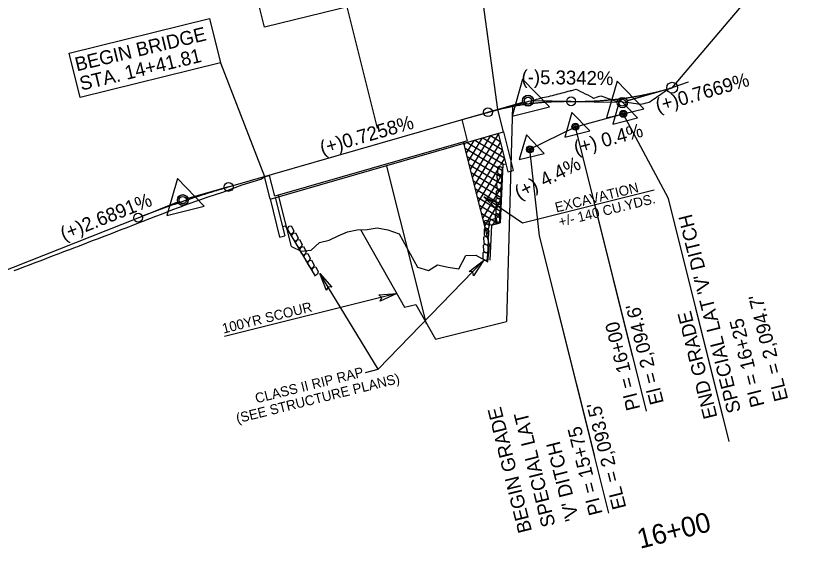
# Model space of a CAD drawing. Extents: x 1030663 to 1033857, y 654635 to 657099.
# Drawn here: x 1031298.2 to 1031692.3, y 655961.2 to 656230.1 of the extents above; entities that cross this region are included whole.
import ezdxf

# ---------------------------------------------------------------- set-up
doc = ezdxf.new("R2010")
doc.units = 0
for name, color, linetype in [('Default', 7, 'Continuous'), ('Exist Vertical Profile Ground Line', 7, 'Continuous'), ('Exist Vertical Profile Horizontal Axis Label Major', 7, 'Continuous'), ('Prop CMT PFL Bottom Envelope', 7, 'Continuous'), ('Prop Grid Mask', 7, 'Continuous'), ('Prop PFL Text', 7, 'Continuous'), ('Prop PFL VPI Symbol CELL', 7, 'Continuous'), ('Prop Terminator CELL', 7, 'Continuous'), ('Prop Vertical Profile Curve Label', 7, 'Continuous'), ('Prop Vertical Profile Ditch Grade Right', 7, 'Continuous'), ('Prop Vertical Profile Ditch Grade Right Label', 7, 'Continuous'), ('Prop Vertical Profile Grade', 7, 'Continuous'), ('Prop Vertical Profile Grade Label', 7, 'Continuous'), ('Prop VPI Ditch Grade Right Label', 7, 'Continuous'), ('Prop VPI Label', 7, 'Continuous')]:
    doc.layers.add(name, color=color, linetype=linetype)

msp = doc.modelspace()

# ---------------------------------------------------------------- linework, layer by layer
at = {"layer": 'Default'}
for p, q in [((1031480.61, 656173.24), (1031465.38, 656234.47)), ((1031548.7, 656184.39), (1031545.65, 656075.66)), ((1031543.8, 656154.93), (1031545.3, 656155.31)), ((1031505.23, 656074.48), (1031485.37, 656154.12)), ((1031543.8, 656154.93), (1031542.41, 656125.45)), ((1031430.65, 656138.54), (1031431.11, 656138.26)), ((1031434.22, 656123.85), (1031432.78, 656123.49)), ((1031433.94, 656123.78), (1031432.78, 656123.49)), ((1031434.22, 656123.85), (1031449.22, 656098.58)), ((1031538.14, 656124.38), (1031537.3, 656106.59)), ((1031538.14, 656124.38), (1031542.41, 656125.45)), ((1031472.03, 656122.07), (1031494.29, 656082.9)), ((1031494.29, 656082.9), (1031499.91, 656084.3)), ((1031499.91, 656084.3), (1031509.89, 656066.74)), ((1031509.89, 656066.74), (1031545.65, 656075.66))]:
    msp.add_line(p, q, dxfattribs=at)
for points in [[(1031543.29, 656149.86), (1031543.49, 656151.03), (1031543.56, 656153.2), (1031542.08, 656153.93), (1031541.07, 656153.62), (1031541.13, 656150.77), (1031542.11, 656149.9), (1031543.29, 656149.86)], [(1031543.07, 656145.78), (1031543.27, 656146.95), (1031543.35, 656149.12), (1031541.86, 656149.85), (1031540.85, 656149.54), (1031540.91, 656146.69), (1031541.9, 656145.82), (1031543.07, 656145.78)], [(1031542.87, 656141.87), (1031543.07, 656143.03), (1031543.14, 656145.21), (1031541.65, 656145.93), (1031540.64, 656145.63), (1031540.71, 656142.78), (1031541.69, 656141.91), (1031542.87, 656141.87)], [(1031620.06, 656141.89), (1031553.7, 656125.34), (1031534.29, 656138.61)], [(1031542.73, 656137.7), (1031542.93, 656138.87), (1031543, 656141.04), (1031541.51, 656141.77), (1031540.5, 656141.46), (1031540.57, 656138.61), (1031541.55, 656137.74), (1031542.73, 656137.7)], [(1031542.55, 656133.68), (1031542.75, 656134.85), (1031542.82, 656137.03), (1031541.33, 656137.75), (1031540.32, 656137.45), (1031540.39, 656134.6), (1031541.37, 656133.72), (1031542.55, 656133.68)], [(1031542.38, 656129.76), (1031542.58, 656130.93), (1031542.66, 656133.1), (1031541.17, 656133.83), (1031540.16, 656133.52), (1031540.22, 656130.67), (1031541.21, 656129.8), (1031542.38, 656129.76)], [(1031537.19, 656124.49), (1031538.37, 656124.61), (1031540.48, 656125.13), (1031540.78, 656126.76), (1031540.21, 656127.65), (1031537.48, 656126.82), (1031536.91, 656125.63), (1031537.19, 656124.49)], [(1031542.08, 656125.87), (1031542.28, 656127.04), (1031542.36, 656129.21), (1031540.87, 656129.94), (1031539.86, 656129.63), (1031539.92, 656126.78), (1031540.9, 656125.91), (1031542.08, 656125.87)], [(1031436.97, 656119.6), (1031436.24, 656120.54), (1031435.16, 656122.42), (1031436.13, 656123.76), (1031437.16, 656123.97), (1031438.45, 656121.42), (1031437.99, 656120.19), (1031436.97, 656119.6)], [(1031536.67, 656122.62), (1031536.87, 656123.79), (1031536.94, 656125.97), (1031535.46, 656126.69), (1031534.45, 656126.39), (1031534.51, 656123.53), (1031535.49, 656122.66), (1031536.67, 656122.62)], [(1031439.08, 656116.1), (1031438.35, 656117.04), (1031437.26, 656118.93), (1031438.24, 656120.27), (1031439.27, 656120.47), (1031440.55, 656117.92), (1031440.09, 656116.69), (1031439.08, 656116.1)], [(1031536.53, 656118.46), (1031536.73, 656119.63), (1031536.8, 656121.8), (1031535.31, 656122.53), (1031534.3, 656122.22), (1031534.37, 656119.37), (1031535.35, 656118.5), (1031536.53, 656118.46)], [(1031441.09, 656112.74), (1031440.37, 656113.68), (1031439.28, 656115.57), (1031440.25, 656116.91), (1031441.29, 656117.11), (1031442.57, 656114.56), (1031442.11, 656113.33), (1031441.09, 656112.74)], [(1031536.35, 656114.44), (1031536.55, 656115.61), (1031536.62, 656117.78), (1031535.14, 656118.51), (1031534.12, 656118.21), (1031534.19, 656115.35), (1031535.17, 656114.48), (1031536.35, 656114.44)], [(1031443.17, 656109.13), (1031442.45, 656110.07), (1031441.36, 656111.95), (1031442.33, 656113.29), (1031443.37, 656113.5), (1031444.65, 656110.95), (1031444.19, 656109.72), (1031443.17, 656109.13)], [(1031536.18, 656110.52), (1031536.38, 656111.69), (1031536.46, 656113.86), (1031534.97, 656114.59), (1031533.96, 656114.28), (1031534.02, 656111.43), (1031535.01, 656110.56), (1031536.18, 656110.52)], [(1031445.22, 656105.67), (1031444.49, 656106.61), (1031443.4, 656108.49), (1031444.38, 656109.83), (1031445.41, 656110.04), (1031446.69, 656107.49), (1031446.23, 656106.26), (1031445.22, 656105.67)], [(1031535.88, 656106.63), (1031536.08, 656107.79), (1031536.16, 656109.97), (1031534.67, 656110.69), (1031533.66, 656110.39), (1031533.72, 656107.54), (1031534.71, 656106.67), (1031535.88, 656106.63)], [(1031447.21, 656102.28), (1031446.48, 656103.22), (1031445.39, 656105.1), (1031446.37, 656106.44), (1031447.4, 656106.65), (1031448.68, 656104.1), (1031448.22, 656102.87), (1031447.21, 656102.28)], [(1031474.6, 656050.03), (1031481.01, 656051.62), (1031534.12, 656106.4)], [(1031449.3, 656098.99), (1031448.57, 656099.92), (1031447.49, 656101.81), (1031448.46, 656103.15), (1031449.49, 656103.36), (1031450.78, 656100.81), (1031450.32, 656099.57), (1031449.3, 656098.99)], [(1031481.01, 656051.62), (1031451.48, 656099.86)], [(1031490.39, 656089.75), (1031403.4, 656068.06)]]:
    msp.add_lwpolyline(points, dxfattribs=at)
at = {"layer": 'Exist Vertical Profile Ground Line'}
for p, q in [((1031525.96, 656166.87), (1031523.27, 656177.63)), ((1031525.96, 656166.87), (1031428.85, 656138.86)), ((1031537, 656114.32), (1031524.03, 656166.31)), ((1031423.97, 656148.84), (1031426.22, 656149.4)), ((1031428.85, 656138.86), (1031426.22, 656149.4)), ((1031437.24, 656113.49), (1031430.77, 656139.41))]:
    msp.add_line(p, q, dxfattribs=at)
for points in [[(1031523.27, 656177.63), (1031546, 656183.78), (1031552.12, 656185.56), (1031555.91, 656186.58), (1031556.9, 656186.84), (1031557.88, 656187.1), (1031558.87, 656187.36), (1031559.86, 656187.62), (1031560.84, 656187.88), (1031561.83, 656188.13), (1031562.82, 656188.39), (1031563.8, 656188.66), (1031564.79, 656188.91), (1031565.79, 656189.09), (1031566.89, 656189.29), (1031567.79, 656189.52), (1031568.78, 656189.78), (1031569.76, 656190.04), (1031570.75, 656190.3), (1031571.74, 656190.55), (1031572.72, 656190.81), (1031573.71, 656191.07), (1031574.7, 656191.33), (1031575.68, 656191.59), (1031576.67, 656191.85), (1031577.66, 656192.1), (1031577.97, 656192.19), (1031578.64, 656192.35), (1031579.63, 656192.6), (1031580.71, 656192.87), (1031581.79, 656192.37), (1031582.98, 656191.81), (1031584.18, 656191.23), (1031585.38, 656190.63), (1031586.58, 656190.02), (1031587.79, 656189.38), (1031589.01, 656188.73), (1031589.57, 656188.42), (1031590.09, 656188.59), (1031591.07, 656188.9), (1031592.05, 656189.19), (1031593.26, 656189.53), (1031594.13, 656189.25), (1031595.28, 656188.87), (1031596.43, 656188.48), (1031597.58, 656188.08), (1031598.73, 656187.67), (1031599.89, 656187.24), (1031601.04, 656186.82), (1031602.12, 656186.74), (1031603.19, 656186.65), (1031604.27, 656186.54), (1031605.35, 656186.43), (1031606.43, 656186.31), (1031607.51, 656186.17), (1031608.6, 656186.03), (1031609.69, 656185.88), (1031611.04, 656185.67), (1031611.87, 656185.55), (1031613.06, 656185.36), (1031613.97, 656185.55), (1031614.97, 656185.76), (1031615.97, 656185.98), (1031616.97, 656186.19), (1031617.57, 656186.31), (1031617.92, 656186.57), (1031618.81, 656187.21), (1031619.71, 656187.84), (1031620.6, 656188.47), (1031621.5, 656189.1), (1031622.39, 656189.72), (1031623.29, 656190.33), (1031624.19, 656190.94), (1031625.09, 656191.54), (1031626.36, 656192.39), (1031627.42, 656193.05), (1031627.86, 656193.44), (1031629.13, 656193.75), (1031637.36, 656196.59), (1031637.36, 656196.59)], [(1031297.49, 656101.37), (1031299.41, 656102.11), (1031302.3, 656103.22), (1031305.2, 656104.32), (1031308.09, 656105.43), (1031310.98, 656106.54), (1031313.87, 656107.65), (1031316.76, 656108.76), (1031319.65, 656109.87), (1031321.39, 656110.54), (1031322.55, 656110.98), (1031323.5, 656111.34), (1031323.82, 656111.45), (1031325.45, 656112.06), (1031328.34, 656113.14), (1031329.49, 656113.57), (1031330.74, 656114.06), (1031331.23, 656114.25), (1031334.12, 656115.37), (1031337.01, 656116.49), (1031339.9, 656117.61), (1031342.79, 656118.73), (1031345.68, 656119.85), (1031348.57, 656120.97), (1031351.46, 656122.08), (1031354.35, 656123.2), (1031355.64, 656123.7), (1031357.24, 656124.32), (1031360.13, 656125.45), (1031363.01, 656126.58), (1031363.62, 656126.81), (1031365.9, 656127.69), (1031368.79, 656128.81), (1031371.68, 656129.92), (1031374.57, 656131.03), (1031377.47, 656132.15), (1031380.36, 656133.26), (1031381.79, 656133.81), (1031383.26, 656134.33), (1031386.17, 656135.36), (1031389.08, 656136.39), (1031391.99, 656137.41), (1031392.45, 656137.58), (1031395.33, 656138.66), (1031402.61, 656140.95), (1031412.43, 656144.62), (1031421.86, 656147.54), (1031423.97, 656148.84)], [(1031437.24, 656113.49), (1031442.14, 656111.13), (1031447.16, 656111.66), (1031451.35, 656115.5), (1031456.21, 656116.71), (1031460.8, 656118.94), (1031465.46, 656120.91), (1031470.34, 656122.03), (1031475.46, 656122.14), (1031480.4, 656123.01), (1031485.82, 656121.93), (1031491.45, 656120), (1031500.81, 656103.13), (1031506.38, 656101.45), (1031510.81, 656104.36), (1031516.25, 656103.19), (1031521.63, 656102.28), (1031525.13, 656108.92), (1031530.22, 656109.2), (1031536.23, 656105.74), (1031537, 656114.32)]]:
    msp.add_lwpolyline(points, dxfattribs=at)
at = {"layer": 'Prop CMT PFL Bottom Envelope'}
for p, q in [((1031544.13, 656171.38), (1031541.32, 656182.67)), ((1031426.46, 656137.46), (1031544.13, 656171.38)), ((1031544.13, 656171.38), (1031548.97, 656151.97)), ((1031525.43, 656160.72), (1031529.26, 656167.09)), ((1031526.46, 656156.6), (1031533.49, 656168.31)), ((1031527.48, 656152.48), (1031537.72, 656169.53)), ((1031528.51, 656148.37), (1031541.6, 656170.16)), ((1031529.71, 656167.22), (1031544.56, 656158.3)), ((1031533.65, 656168.35), (1031543.53, 656162.42)), ((1031537.59, 656169.49), (1031542.51, 656166.53)), ((1031541.46, 656170.71), (1031546.3, 656151.3)), ((1031524.4, 656164.83), (1031525.03, 656165.87)), ((1031524.82, 656163.16), (1031543.66, 656151.84)), ((1031525.78, 656166.09), (1031544.14, 656155.05)), ((1031529.54, 656144.25), (1031542.63, 656166.04)), ((1031530.56, 656140.13), (1031543.65, 656161.92)), ((1031525.85, 656159.04), (1031543.49, 656148.44)), ((1031542.8, 656154.68), (1031544.68, 656157.81)), ((1031526.87, 656154.93), (1031543.33, 656145.04)), ((1031531.59, 656136.02), (1031542.64, 656154.4)), ((1031546.3, 656151.3), (1031548.97, 656151.97)), ((1031426.42, 656137.64), (1031423.62, 656148.84)), ((1031527.9, 656150.81), (1031543.17, 656141.63)), ((1031532.61, 656131.9), (1031543.58, 656150.14)), ((1031528.93, 656146.69), (1031543.01, 656138.23)), ((1031533.64, 656127.78), (1031543.28, 656143.82)), ((1031529.95, 656142.58), (1031541.74, 656135.49)), ((1031426.42, 656137.64), (1031431.26, 656118.23)), ((1031429.09, 656138.3), (1031433.92, 656118.9)), ((1031530.98, 656138.46), (1031542.69, 656131.42)), ((1031534.72, 656123.76), (1031542.98, 656137.5)), ((1031532.01, 656134.34), (1031542.53, 656128.02)), ((1031533.13, 656130.17), (1031541.42, 656125.19)), ((1031538.67, 656124.5), (1031542.68, 656131.18)), ((1031534.06, 656126.11), (1031537.28, 656124.17)), ((1031535.08, 656121.99), (1031536.83, 656120.94)), ((1031535.69, 656119.55), (1031536.86, 656121.49)), ((1031431.26, 656118.23), (1031433.92, 656118.9))]:
    msp.add_line(p, q, dxfattribs=at)
at = {"layer": 'Prop Grid Mask'}
for points in [[(1031413.95, 656263.49), (1031510.89, 656287.51), (1031520.64, 656248.16), (1031423.7, 656224.15)], [(1031325.16, 656211.18), (1031395.98, 656228.62), (1031401.5, 656206.18), (1031330.68, 656188.74)]]:
    msp.add_lwpolyline(points, close=True, dxfattribs=at)
at = {"layer": 'Prop PFL VPI Symbol CELL'}
for p, q in [((1031553.77, 656198.03), (1031548.45, 656179.39)), ((1031553.77, 656198.03), (1031567.29, 656184.09)), ((1031601.36, 656197.04), (1031596.04, 656178.4)), ((1031601.36, 656197.04), (1031614.88, 656183.1)), ((1031548.45, 656179.39), (1031567.29, 656184.09)), ((1031596.04, 656178.4), (1031614.88, 656183.1)), ((1031379.73, 656147.87), (1031374.41, 656129.23)), ((1031379.73, 656147.87), (1031393.26, 656133.93)), ((1031374.41, 656129.23), (1031393.26, 656133.93))]:
    msp.add_line(p, q, dxfattribs=at)
for centre, radius in [((1031556.49, 656187.14), 2.62), ((1031556.49, 656187.14), 1.8), ((1031604.08, 656186.15), 2.62), ((1031604.08, 656186.15), 1.8), ((1031382.46, 656136.98), 2.62), ((1031382.46, 656136.98), 1.8)]:
    msp.add_circle(centre, radius, dxfattribs=at)
at = {"layer": 'Prop Terminator CELL'}
for points in [[(1031540.85, 656132.25), (1031534.29, 656138.61), (1031542.67, 656134.83), (1031540.81, 656134.15)], [(1031526.75, 656101.01), (1031534.12, 656106.4), (1031528.97, 656098.79), (1031528.63, 656100.73)], [(1031454.86, 656091.38), (1031451.48, 656099.86), (1031457.57, 656092.98), (1031455.61, 656093.13)], [(1031481.28, 656089.08), (1031490.39, 656089.75), (1031482, 656086.01), (1031482.73, 656087.84)]]:
    msp.add_lwpolyline(points, close=True, dxfattribs=at)
at = {"layer": 'Prop Vertical Profile Curve Label'}
for centre in [(1031578.23, 656186.79), (1031536.3, 656181.32), (1031405.54, 656143.63), (1031359.95, 656128.05)]:
    msp.add_circle(centre, 2.25, dxfattribs=at)
at = {"layer": 'Prop Vertical Profile Ditch Grade Right'}
msp.add_lwpolyline([(1031557.47, 656162.58), (1031580.39, 656173.97), (1031604.53, 656180.5)], dxfattribs=at)
at = {"layer": 'Prop Vertical Profile Grade'}
for p, q in [((1031628.12, 656193.34), (1031629.16, 656193.64)), ((1031405.54, 656143.63), (1031536.3, 656181.32)), ((1031270.87, 656092.67), (1031359.95, 656128.05))]:
    msp.add_line(p, q, dxfattribs=at)
for points in [[(1031578.23, 656186.79), (1031579.26, 656186.77), (1031580.29, 656186.76), (1031581.32, 656186.76), (1031582.35, 656186.76), (1031583.38, 656186.77), (1031584.41, 656186.79), (1031585.43, 656186.81), (1031586.46, 656186.84), (1031587.48, 656186.87), (1031588.5, 656186.91), (1031589.52, 656186.96), (1031590.54, 656187.01), (1031591.56, 656187.06), (1031592.57, 656187.13), (1031593.58, 656187.2), (1031594.6, 656187.27), (1031595.61, 656187.35), (1031596.61, 656187.44), (1031597.62, 656187.53), (1031598.63, 656187.63), (1031599.63, 656187.73), (1031600.64, 656187.84), (1031601.64, 656187.96), (1031602.64, 656188.08), (1031603.64, 656188.21), (1031604.63, 656188.34), (1031605.63, 656188.48), (1031606.62, 656188.63), (1031607.62, 656188.78), (1031608.61, 656188.94), (1031609.6, 656189.1), (1031610.59, 656189.27), (1031611.57, 656189.45), (1031612.56, 656189.63), (1031613.54, 656189.82), (1031614.52, 656190.01), (1031615.51, 656190.21), (1031616.48, 656190.42), (1031617.46, 656190.63), (1031618.44, 656190.84), (1031619.41, 656191.07), (1031620.39, 656191.3), (1031621.36, 656191.53), (1031622.33, 656191.77), (1031623.3, 656192.02), (1031624.27, 656192.27), (1031625.23, 656192.53), (1031626.2, 656192.79), (1031627.16, 656193.06), (1031628.12, 656193.34)], [(1031536.3, 656181.32), (1031537.11, 656181.55), (1031537.92, 656181.78), (1031538.73, 656182), (1031539.54, 656182.22), (1031540.36, 656182.43), (1031541.17, 656182.63), (1031541.99, 656182.83), (1031542.8, 656183.03), (1031543.62, 656183.22), (1031544.44, 656183.41), (1031545.26, 656183.59), (1031546.08, 656183.76), (1031546.91, 656183.93), (1031547.73, 656184.1), (1031548.56, 656184.26), (1031549.38, 656184.42), (1031550.21, 656184.57), (1031551.04, 656184.71), (1031551.87, 656184.86), (1031552.7, 656184.99), (1031553.54, 656185.12), (1031554.37, 656185.25), (1031555.2, 656185.37), (1031556.04, 656185.49), (1031556.88, 656185.6), (1031557.72, 656185.71), (1031558.56, 656185.81), (1031559.4, 656185.9), (1031560.24, 656186), (1031561.09, 656186.08), (1031561.93, 656186.17), (1031562.78, 656186.24), (1031563.63, 656186.32), (1031564.48, 656186.38), (1031565.33, 656186.44), (1031566.18, 656186.5), (1031567.03, 656186.55), (1031567.88, 656186.6), (1031568.74, 656186.64), (1031569.6, 656186.68), (1031570.45, 656186.71), (1031571.31, 656186.74), (1031572.17, 656186.76), (1031573.03, 656186.78), (1031573.9, 656186.8), (1031574.76, 656186.8), (1031575.62, 656186.81), (1031576.49, 656186.8), (1031577.36, 656186.8), (1031578.23, 656186.79)], [(1031359.95, 656128.05), (1031360.85, 656128.4), (1031361.75, 656128.76), (1031362.66, 656129.11), (1031363.56, 656129.46), (1031364.46, 656129.81), (1031365.36, 656130.16), (1031366.27, 656130.5), (1031367.17, 656130.85), (1031368.07, 656131.19), (1031368.98, 656131.53), (1031369.88, 656131.87), (1031370.79, 656132.2), (1031371.7, 656132.54), (1031372.6, 656132.87), (1031373.51, 656133.2), (1031374.42, 656133.53), (1031375.32, 656133.86), (1031376.23, 656134.18), (1031377.14, 656134.51), (1031378.05, 656134.83), (1031378.96, 656135.15), (1031379.87, 656135.47), (1031380.78, 656135.78), (1031381.69, 656136.1), (1031382.6, 656136.41), (1031383.51, 656136.72), (1031384.43, 656137.03), (1031385.34, 656137.34), (1031386.25, 656137.64), (1031387.17, 656137.95), (1031388.08, 656138.25), (1031389, 656138.55), (1031389.91, 656138.85), (1031390.83, 656139.14), (1031391.74, 656139.44), (1031392.66, 656139.73), (1031393.57, 656140.02), (1031394.49, 656140.31), (1031395.41, 656140.6), (1031396.33, 656140.88), (1031397.25, 656141.17), (1031398.17, 656141.45), (1031399.09, 656141.73), (1031400.01, 656142), (1031400.93, 656142.28), (1031401.85, 656142.56), (1031402.77, 656142.83), (1031403.69, 656143.1), (1031404.61, 656143.37), (1031405.54, 656143.63)]]:
    msp.add_spline(points, degree=3, dxfattribs=at)
at = {"layer": 'Prop Vertical Profile Grade Label'}
for p, q in [((1031629.16, 656193.64), (1031706.57, 656284.94)), ((1031541.32, 656182.67), (1031532.93, 656243.67)), ((1031401.5, 656206.18), (1031423.62, 656148.84))]:
    msp.add_line(p, q, dxfattribs=at)
at = {"layer": 'Prop VPI Ditch Grade Right Label'}
for p, q in [((1031602.71, 656187.76), (1031599.16, 656175.33)), ((1031602.71, 656187.76), (1031611.73, 656178.46)), ((1031578.58, 656181.22), (1031575.03, 656168.8)), ((1031578.58, 656181.22), (1031587.59, 656171.93)), ((1031627.35, 656137.74), (1031604.53, 656180.5)), ((1031599.16, 656175.33), (1031611.73, 656178.46)), ((1031575.03, 656168.8), (1031587.59, 656171.93)), ((1031616.17, 656030.47), (1031580.39, 656173.97)), ((1031609.22, 656058.35), (1031580.39, 656173.97)), ((1031555.65, 656169.84), (1031552.1, 656157.41)), ((1031555.65, 656169.84), (1031564.67, 656160.54)), ((1031552.1, 656157.41), (1031564.67, 656160.54)), ((1031562.35, 656118.95), (1031557.47, 656162.58)), ((1031657.92, 656015.12), (1031627.35, 656137.74)), ((1031654.76, 656027.79), (1031627.35, 656137.74)), ((1031597.26, 655978.95), (1031562.35, 656118.95)), ((1031590.09, 656007.7), (1031562.35, 656118.95))]:
    msp.add_line(p, q, dxfattribs=at)
for centre, radius in [((1031604.53, 656180.5), 1.75), ((1031604.53, 656180.5), 1.2), ((1031604.53, 656180.5), 0.5), ((1031580.39, 656173.97), 1.75), ((1031580.39, 656173.97), 1.2), ((1031580.39, 656173.97), 0.5), ((1031557.47, 656162.58), 1.75), ((1031557.47, 656162.58), 1.2), ((1031557.47, 656162.58), 0.5)]:
    msp.add_circle(centre, radius, dxfattribs=at)
at = {"layer": 'Prop VPI Label'}
for p, q in [((1031628.12, 656193.34), (1031606.54, 656187.07)), ((1031628.12, 656193.34), (1031606.74, 656187.13)), ((1031578.23, 656186.79), (1031559.12, 656187.1)), ((1031578.23, 656186.79), (1031559.24, 656187.1)), ((1031578.23, 656186.79), (1031601.47, 656186.4)), ((1031578.23, 656186.79), (1031601.35, 656186.4)), ((1031536.3, 656181.32), (1031553.97, 656186.42)), ((1031536.3, 656181.32), (1031553.85, 656186.38)), ((1031405.54, 656143.63), (1031384.98, 656137.71)), ((1031405.54, 656143.63), (1031385.1, 656137.74)), ((1031359.95, 656128.05), (1031380.02, 656136.01)), ((1031359.95, 656128.05), (1031379.9, 656135.97))]:
    msp.add_line(p, q, dxfattribs=at)
for centre in [(1031629.16, 656193.64), (1031556.49, 656187.14), (1031382.46, 656136.98)]:
    msp.add_circle(centre, 2.75, dxfattribs=at)

# ---------------------------------------------------------------- texts
at = {"layer": 'Exist Vertical Profile Horizontal Axis Label Major'}
msp.add_text('16+00', height=10, rotation=14, dxfattribs=at).set_placement((1031612.95, 655960.95))
at = {"layer": 'Prop PFL Text'}
for s, p in [('EXCAVATION', (1031570.79, 656130.69)), ('+/- 140 CU.YDS.', (1031572.6, 656123.42)), ('100YR SCOUR', (1031402.98, 656069.58)), ('(SEE STRUCTURE PLANS)', (1031410.03, 656024.27)), ('CLASS II RIP RAP', (1031419.61, 656034.39))]:
    msp.add_text(s, height=5, rotation=13.9999, dxfattribs=at).set_placement(p)
at = {"layer": 'Prop Vertical Profile Ditch Grade Right Label'}
for s, rotation, p in [('(+) 0.4%', 15.1458, (1031580.66, 656159.82)), ('(+) 4.4%', 26.4074, (1031551.89, 656137.16))]:
    msp.add_text(s, height=7, rotation=rotation, dxfattribs=at).set_placement(p)
at = {"layer": 'Prop Vertical Profile Grade Label'}
for s, rotation, p in [('BEGIN BRIDGE', 13.4999, (1031329.05, 656201.9)), ('STA. 14+41.81', 13.4999, (1031331.38, 656192.17)), ('(-)5.3342%', 359.0537, (1031553.17, 656195.69)), ('(+)0.7669%', 16.2048, (1031621.91, 656181.12)), ('(+)0.7258%', 16.0784, (1031452.74, 656159.74)), ('(+)2.6891%', 21.6577, (1031322.41, 656116.36))]:
    msp.add_text(s, height=7, rotation=rotation, dxfattribs=at).set_placement(p)
at = {"layer": 'Prop VPI Ditch Grade Right Label'}
for s, p in [("SPECIAL LAT 'V' DITCH", (1031663.88, 656030.48)), ("EL = 2,094.7'", (1031687.66, 656036.4)), ("El = 2,094.6'", (1031624.98, 656034.73)), ('END GRADE', (1031652, 656027.51)), ('PI = 16+25', (1031675.77, 656033.44)), ('PI = 16+00', (1031613.09, 656031.77)), ("EL = 2,093.5'", (1031606.06, 655981.85)), ('BEGIN GRADE', (1031558.52, 655969.99)), ('SPECIAL LAT', (1031570.4, 655972.96)), ('PI = 15+75', (1031594.18, 655978.88)), ("'V' DITCH", (1031582.29, 655975.92))]:
    msp.add_text(s, height=7, rotation=104, dxfattribs=at).set_placement(p)

doc.saveas('drawing.dxf')
